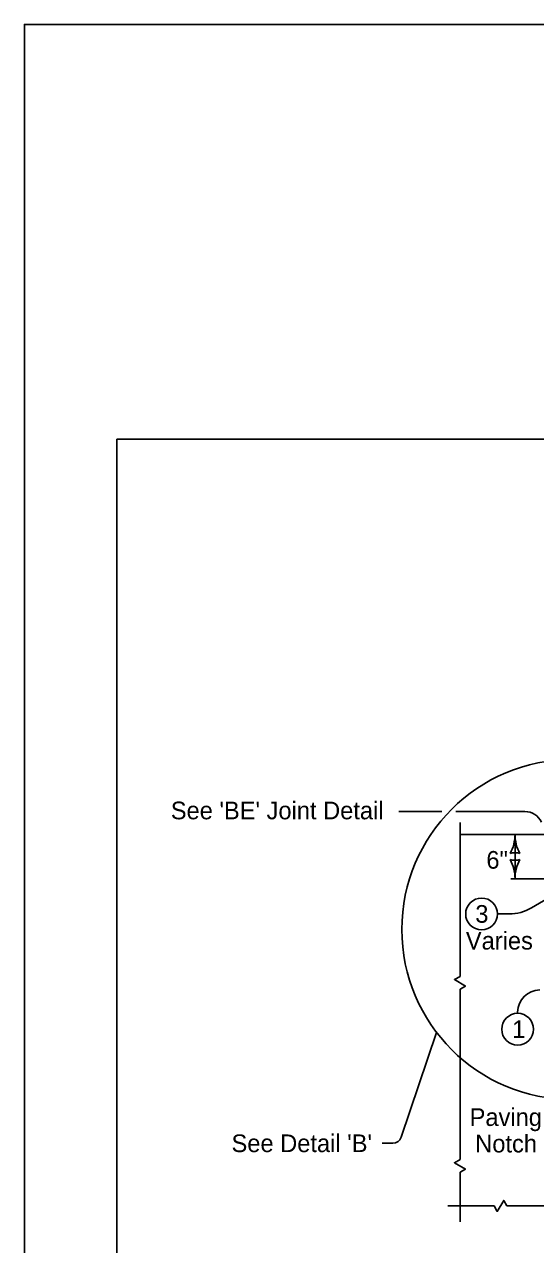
# Model space of a CAD drawing. Extents: x -2135039 to -2120895, y -2139150 to -2136566.
# Drawn here: x -2135039 to -2134461, y -2137948 to -2136566 of the extents above; entities that cross this region are included whole.
import ezdxf

# ---------------------------------------------------------------- set-up
doc = ezdxf.new("R2010")
doc.units = 0
for name, color, linetype in [('dsnDOTLogo', 7, 'Continuous'), ('dsnStdLabel', 7, 'Continuous'), ('dsnStdLineWork', 7, 'Continuous'), ('dsnStdNote', 7, 'Continuous'), ('Level 1', 7, 'Continuous'), ('Level 2', 7, 'Continuous'), ('Level 3', 7, 'Continuous')]:
    doc.layers.add(name, color=color, linetype=linetype)

msp = doc.modelspace()

# ---------------------------------------------------------------- linework, layer by layer
at = {"layer": 'dsnDOTLogo'}
msp.add_lwpolyline([(-2135038.9, -2139150.4), (-2131694.9, -2139150.4), (-2131694.9, -2136566.4), (-2135038.9, -2136566.4)], close=True, dxfattribs=at)
at = {"layer": 'dsnStdLabel'}
for p, q in [((-2134484.1, -2137483.3), (-2134484.1, -2137533.4)), ((-2134420.3, -2137533.4), (-2134489, -2137533.4)), ((-2134413.5, -2137535.8), (-2134465.5, -2137566.4)), ((-2134490.8, -2137573.3), (-2134503.9, -2137573.3)), ((-2134572.8, -2137707.4), (-2134612.7, -2137826.1)), ((-2134622.2, -2137832.9), (-2134634.4, -2137832.9))]:
    msp.add_line(p, q, dxfattribs=at)
msp.add_circle((-2134419.6, -2137590.9), 192.5, dxfattribs=at)
for centre, radius, start, end in [((-2134530.2, -2137483.3), 46.1, 331.9275, 360), ((-2134530.2, -2137483.3), 46.1, 331.9275, 360), ((-2134438, -2137483.3), 46.1, 180, 208.0725), ((-2134438, -2137483.3), 46.1, 180, 208.0725), ((-2134484.1, -2137521.9), 17.8, 72.2666, 107.7334), ((-2134484.1, -2137521.9), 17.8, 72.2666, 107.7334), ((-2134484.1, -2137494.8), 17.8, 252.2666, 287.7333), ((-2134530.2, -2137533.4), 46.1, 360, 28.0725), ((-2134438, -2137533.4), 46.1, 151.9275, 180)]:
    msp.add_arc(centre, radius, start, end, dxfattribs=at)
at = {"layer": 'dsnStdLineWork'}
for p, q in [((-2134546.3, -2137469.9), (-2134546.3, -2137554.9)), ((-2134423.6, -2137483.3), (-2134546.3, -2137483.3)), ((-2134546.3, -2137554.9), (-2134546.3, -2137644.1)), ((-2134546.3, -2137658.5), (-2134546.3, -2137851.3)), ((-2134546.3, -2137865.7), (-2134546.3, -2137921.8)), ((-2134507.7, -2137903.8), (-2134560.1, -2137903.8)), ((-2134440.8, -2137903.8), (-2134493.2, -2137903.8))]:
    msp.add_line(p, q, dxfattribs=at)
for points in [[(-2134546.3, -2137658.5), (-2134540.1, -2137654.9), (-2134552.6, -2137647.7), (-2134546.3, -2137644.1)], [(-2134546.3, -2137865.7), (-2134540.1, -2137862.1), (-2134552.6, -2137854.9), (-2134546.3, -2137851.3)], [(-2134493.2, -2137903.8), (-2134496.8, -2137897.5), (-2134504.1, -2137910), (-2134507.7, -2137903.8)]]:
    msp.add_lwpolyline(points, dxfattribs=at)
at = {"layer": 'dsnStdNote'}
msp.add_circle((-2134521.9, -2137573.3), 18, dxfattribs=at)
at = {"layer": 'Level 1'}
msp.add_lwpolyline([(-2134934.4, -2137035.9), (-2131799.4, -2137035.9), (-2131799.4, -2139045.9), (-2134934.4, -2139045.9)], close=True, dxfattribs=at)
at = {"layer": 'Level 2'}
msp.add_circle((-2134481.1, -2137703.8), 18, dxfattribs=at)
for centre, radius, start, end in [((-2134490.8, -2137523.3), 50, 270, 300.4766), ((-2134456.1, -2137684.4), 25, 90, 180), ((-2134622.2, -2137822.9), 10, 270, 341.4058)]:
    msp.add_arc(centre, radius, start, end, dxfattribs=at)
at = {"layer": 'Level 3'}
for p, q in [((-2134566.9, -2137457.4), (-2134615.5, -2137457.4)), ((-2134472.8, -2137457.4), (-2134551.1, -2137457.4)), ((-2134481.1, -2137685.8), (-2134481.1, -2137684.4))]:
    msp.add_line(p, q, dxfattribs=at)
msp.add_arc((-2134472.8, -2137477.6), 20.2, 23.6401, 90, dxfattribs=at)

# ---------------------------------------------------------------- texts
at = {"layer": 'dsnStdLabel'}
for s, p in [('6"', (-2134516.5, -2137522.1)), ('Varies', (-2134539.7, -2137613.6)), ('Paving', (-2134535.4, -2137813.3)), ("See Detail 'B'", (-2134804.7, -2137842.9)), ('Notch', (-2134529.1, -2137843.3))]:
    msp.add_text(s, height=20, dxfattribs=at).set_placement(p)
at = {"layer": 'dsnStdNote'}
msp.add_text('3', height=20, dxfattribs=at).set_placement((-2134529, -2137583.3))
at = {"layer": 'Level 3'}
for s, p in [("See 'BE' Joint Detail", (-2134873.4, -2137466.2)), ('1', (-2134487.3, -2137713.8))]:
    msp.add_text(s, height=20, dxfattribs=at).set_placement(p)

doc.saveas('drawing.dxf')
